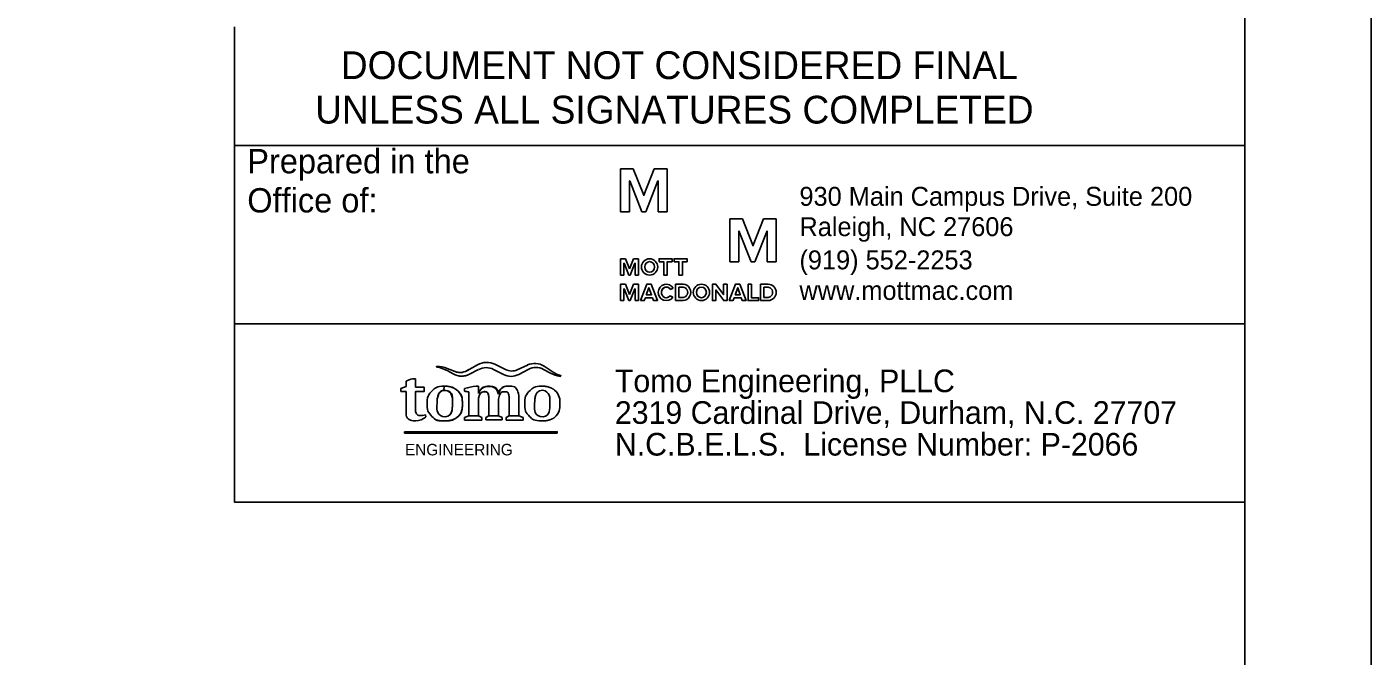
# Model space of a CAD drawing. Extents: x 2467493 to 2469404, y 649492 to 650592.
# Drawn here: x 2468926.4 to 2469192.5, y 650305.4 to 650429.9 of the extents above; entities that cross this region are included whole.
import ezdxf

# ---------------------------------------------------------------- set-up
doc = ezdxf.new("R2010")
doc.units = 0
for name, color, linetype in [('Old_Level_18', 7, 'Continuous'), ('Old_Level_2', 7, 'Continuous'), ('Old_Level_3', 7, 'Continuous'), ('Old_Level_42', 7, 'Continuous'), ('Old_Level_62', 7, 'Continuous'), ('Old_Level_63', 7, 'Continuous'), ('Sheet Sticker Exception Certification CELL', 7, 'Continuous')]:
    doc.layers.add(name, color=color, linetype=linetype)

msp = doc.modelspace()

# ---------------------------------------------------------------- linework, layer by layer
at = {"layer": 'Old_Level_18'}
msp.add_lwpolyline([(2469167.55, 650567.49), (2467667.55, 650567.49), (2467667.55, 649517.49), (2469167.55, 649517.49)], close=True, dxfattribs=at)
at = {"layer": 'Old_Level_2'}
for p, q in [((2469046.48, 650401.84), (2469043.96, 650401.84)), ((2469043.96, 650401.84), (2469043.96, 650393.34)), ((2469048.53, 650396.59), (2469046.48, 650401.84)), ((2469050.64, 650401.84), (2469048.58, 650396.59)), ((2469053.16, 650401.84), (2469050.64, 650401.84)), ((2469053.16, 650393.34), (2469053.16, 650401.84)), ((2469045.75, 650393.34), (2469045.75, 650399.45)), ((2469045.75, 650399.45), (2469045.78, 650399.45)), ((2469045.78, 650399.45), (2469048.17, 650393.34)), ((2469048.95, 650393.34), (2469051.34, 650399.48)), ((2469051.34, 650399.48), (2469051.37, 650399.48)), ((2469051.37, 650399.48), (2469051.37, 650393.34)), ((2469048.53, 650396.51), (2469048.53, 650396.59)), ((2469048.58, 650396.51), (2469048.53, 650396.51)), ((2469048.58, 650396.59), (2469048.58, 650396.51)), ((2469043.96, 650393.34), (2469045.75, 650393.34)), ((2469048.17, 650393.34), (2469048.95, 650393.34)), ((2469051.37, 650393.34), (2469053.16, 650393.34)), ((2469068.09, 650391.94), (2469065.57, 650391.94)), ((2469065.57, 650391.94), (2469065.57, 650383.44)), ((2469070.15, 650386.69), (2469068.09, 650391.94)), ((2469072.25, 650391.94), (2469070.2, 650386.69)), ((2469074.77, 650391.94), (2469072.25, 650391.94)), ((2469074.77, 650383.44), (2469074.77, 650391.94)), ((2469067.37, 650383.44), (2469067.37, 650389.55)), ((2469067.37, 650389.55), (2469067.39, 650389.55)), ((2469067.39, 650389.55), (2469069.78, 650383.44)), ((2469070.56, 650383.44), (2469072.95, 650389.57)), ((2469072.95, 650389.57), (2469072.98, 650389.57)), ((2469072.98, 650389.57), (2469072.98, 650383.44)), ((2469070.15, 650386.61), (2469070.15, 650386.69)), ((2469070.2, 650386.61), (2469070.15, 650386.61)), ((2469070.2, 650386.69), (2469070.2, 650386.61)), ((2469044.92, 650384.04), (2469043.96, 650384.04)), ((2469043.96, 650384.04), (2469043.96, 650380.79)), ((2469045.72, 650382.01), (2469044.92, 650384.04)), ((2469046.53, 650384.04), (2469045.72, 650382.01)), ((2469047.49, 650384.04), (2469046.53, 650384.04)), ((2469047.49, 650380.79), (2469047.49, 650384.04)), ((2469047.49, 650380.79), (2469047.49, 650384.04)), ((2469065.57, 650383.44), (2469067.37, 650383.44)), ((2469069.78, 650383.44), (2469070.56, 650383.44)), ((2469072.98, 650383.44), (2469074.77, 650383.44)), ((2469043.96, 650380.79), (2469044.63, 650380.79)), ((2469044.63, 650380.79), (2469044.63, 650383.13)), ((2469044.63, 650383.13), (2469044.66, 650383.13)), ((2469044.63, 650383.13), (2469044.66, 650383.13)), ((2469044.66, 650383.13), (2469045.57, 650380.79)), ((2469045.57, 650380.79), (2469045.88, 650380.79)), ((2469045.88, 650380.79), (2469046.79, 650383.13)), ((2469046.79, 650383.13), (2469046.82, 650383.13)), ((2469046.79, 650383.13), (2469046.82, 650383.13)), ((2469046.79, 650383.13), (2469046.82, 650383.13)), ((2469046.82, 650383.13), (2469046.82, 650380.79)), ((2469046.82, 650380.79), (2469047.49, 650380.79)), ((2469044.92, 650378.99), (2469043.96, 650378.99)), ((2469043.96, 650378.99), (2469043.96, 650375.74)), ((2469044.63, 650375.74), (2469044.63, 650378.08)), ((2469044.63, 650378.08), (2469044.66, 650378.08)), ((2469044.66, 650378.08), (2469045.57, 650375.74)), ((2469045.72, 650376.96), (2469044.92, 650378.99)), ((2469046.53, 650378.99), (2469045.72, 650376.96)), ((2469045.88, 650375.74), (2469046.79, 650378.08)), ((2469047.49, 650378.99), (2469046.53, 650378.99)), ((2469046.79, 650378.08), (2469046.82, 650378.08)), ((2469046.82, 650378.08), (2469046.82, 650375.74)), ((2469047.49, 650375.74), (2469047.49, 650378.99)), ((2469053.83, 650377.93), (2469054.4, 650378.2)), ((2469053.83, 650377.93), (2469054.4, 650378.2)), ((2469056.33, 650378.99), (2469054.85, 650378.99)), ((2469054.85, 650378.99), (2469054.85, 650377.31)), ((2469055.52, 650376.37), (2469055.52, 650378.39)), ((2469055.52, 650378.39), (2469056.33, 650378.39)), ((2469071.67, 650378.99), (2469071.67, 650378.99)), ((2469073.15, 650378.99), (2469071.67, 650378.99)), ((2469071.67, 650378.99), (2469071.67, 650377.31)), ((2469072.34, 650376.37), (2469072.34, 650378.39)), ((2469072.34, 650378.39), (2469073.15, 650378.39)), ((2469073.15, 650378.37), (2469073.15, 650378.37)), ((2469043.96, 650375.74), (2469044.63, 650375.74)), ((2469045.57, 650375.74), (2469045.88, 650375.74)), ((2469046.82, 650375.74), (2469047.49, 650375.74)), ((2469054.32, 650376.41), (2469053.76, 650376.69)), ((2469054.32, 650376.41), (2469053.76, 650376.69)), ((2469054.85, 650377.31), (2469054.85, 650375.74)), ((2469054.85, 650375.74), (2469056.33, 650375.74)), ((2469056.33, 650376.37), (2469055.52, 650376.37)), ((2469071.67, 650377.31), (2469071.67, 650375.74)), ((2469071.67, 650375.74), (2469073.15, 650375.74)), ((2469073.15, 650376.37), (2469072.34, 650376.37))]:
    msp.add_line(p, q, dxfattribs=at)
for points in [[(2469051.57, 650383.44), (2469052.51, 650383.44), (2469052.51, 650380.79), (2469053.21, 650380.79), (2469053.21, 650383.44), (2469054.15, 650383.44), (2469054.15, 650384.04), (2469051.57, 650384.04), (2469051.57, 650383.44)], [(2469054.56, 650383.44), (2469055.5, 650383.44), (2469055.5, 650380.79), (2469056.2, 650380.79), (2469056.2, 650383.44), (2469057.14, 650383.44), (2469057.14, 650384.04), (2469054.56, 650384.04), (2469054.56, 650383.44)], [(2469047.88, 650375.74), (2469048.66, 650375.74), (2469048.87, 650376.29), (2469050.27, 650376.29), (2469050.48, 650375.74), (2469051.24, 650375.74), (2469049.99, 650378.99), (2469049.13, 650378.99), (2469047.88, 650375.74)], [(2469049.05, 650376.89), (2469049.57, 650378.29), (2469050.09, 650376.89), (2469049.05, 650376.89)], [(2469062.8, 650377.85), (2469062.83, 650377.85), (2469064.39, 650375.74), (2469065.04, 650375.74), (2469065.04, 650378.99), (2469064.36, 650378.99), (2469064.36, 650376.94), (2469062.83, 650378.99), (2469062.15, 650378.99), (2469062.15, 650375.74), (2469062.8, 650375.74), (2469062.8, 650377.85)], [(2469065.45, 650375.74), (2469066.23, 650375.74), (2469066.44, 650376.29), (2469067.85, 650376.29), (2469068.05, 650375.74), (2469068.81, 650375.74), (2469067.56, 650378.99), (2469066.7, 650378.99), (2469065.45, 650375.74)], [(2469066.62, 650376.89), (2469067.14, 650378.29), (2469067.66, 650376.89), (2469066.62, 650376.89)], [(2469071.28, 650375.74), (2469071.28, 650376.32), (2469069.87, 650376.32), (2469069.87, 650378.99), (2469069.2, 650378.99), (2469069.2, 650375.74), (2469071.28, 650375.74)], [(2469071.28, 650375.74), (2469071.28, 650376.32), (2469069.87, 650376.32), (2469069.87, 650378.99), (2469069.2, 650378.99), (2469069.2, 650375.74), (2469071.28, 650375.75), (2469071.28, 650376.32)]]:
    msp.add_lwpolyline(points, dxfattribs=at)
msp.add_arc((2469073.15, 650377.37), 1.62, 270, 90, dxfattribs=at)
for centre, major_axis, ratio in [((2469049.7, 650382.41), (0, 1.62), 0.993118), ((2469049.7, 650382.41), (0, 1.06), 0.916103), ((2469059.97, 650377.37), (0, 1.62), 0.993118), ((2469059.97, 650377.37), (0, 1.06), 0.916103)]:
    msp.add_ellipse(centre, major_axis=major_axis, ratio=ratio, dxfattribs=at)
for centre, major_axis, ratio, start_param, end_param in [((2469053.01, 650377.37), (0, 1.62), 0.993118, 5.246647, 10.366427), ((2469053.01, 650377.37), (0, 1.62), 0.993118, 5.246647, 10.366427), ((2469053.01, 650377.37), (0, 1.06), 0.916103, 5.276876, 9.424778), ((2469053.01, 650377.37), (0, 1.06), 0.916103, 5.276876, 10.296021), ((2469056.33, 650377.37), (0, -1.62), 0.930276, 0, 3.141593), ((2469056.33, 650377.38), (0, -1.01), 0.900832, 0, 3.141593), ((2469073.15, 650377.38), (0, -1.01), 0.900832, 0, 3.141593), ((2469053.01, 650377.37), (0, 1.06), 0.916103, 3.141593, 4.012835)]:
    msp.add_ellipse(centre, major_axis=major_axis, ratio=ratio, start_param=start_param, end_param=end_param, dxfattribs=at)
at = {"layer": 'Old_Level_3'}
for p, q in [((2469009.61, 650361.9), (2469010.81, 650361.22)), ((2469009.61, 650361.9), (2469010.81, 650361.22)), ((2469009.64, 650362.33), (2469011.2, 650361.7)), ((2469011.2, 650361.7), (2469009.64, 650362.33)), ((2469013.54, 650361.86), (2469015.64, 650363.05)), ((2469015.64, 650363.05), (2469013.54, 650361.86)), ((2469014.06, 650361.18), (2469015.86, 650362.11)), ((2469014.06, 650361.18), (2469015.86, 650362.11)), ((2469018.8, 650362.12), (2469020.76, 650361.11)), ((2469018.8, 650362.12), (2469020.76, 650361.11)), ((2469019.09, 650363.14), (2469021.2, 650362.09)), ((2469021.2, 650362.09), (2469019.09, 650363.14)), ((2469025.54, 650362.99), (2469023.51, 650362.05)), ((2469025.54, 650362.99), (2469023.51, 650362.05)), ((2469025.68, 650362.13), (2469023.79, 650361.13)), ((2469023.79, 650361.13), (2469025.68, 650362.13)), ((2469030.08, 650361.4), (2469028.72, 650362.12)), ((2469028.72, 650362.12), (2469030.08, 650361.4)), ((2469028.81, 650362.75), (2469030.6, 650361.57)), ((2469030.6, 650361.57), (2469028.81, 650362.75)), ((2469001.49, 650359.81), (2469001.49, 650358.77)), ((2469001.49, 650359.81), (2469001.49, 650358.77)), ((2469002.74, 650360.26), (2469003.38, 650360.26)), ((2469003.38, 650360.26), (2469002.74, 650360.26)), ((2469003.38, 650360.26), (2469003.38, 650358.63)), ((2469003.38, 650358.63), (2469003.38, 650360.26)), ((2469000.44, 650358.31), (2469001.49, 650358.77)), ((2469001.49, 650358.77), (2469000.44, 650358.31)), ((2469000.44, 650357.76), (2469000.44, 650358.31)), ((2469000.44, 650358.31), (2469000.44, 650357.76)), ((2469001.48, 650357.76), (2469000.44, 650357.76)), ((2469000.44, 650357.76), (2469001.48, 650357.76)), ((2469001.48, 650353.35), (2469001.48, 650357.76)), ((2469001.48, 650357.76), (2469001.48, 650353.35)), ((2469003.38, 650358.63), (2469005.08, 650358.63)), ((2469005.08, 650358.63), (2469003.38, 650358.63)), ((2469009.06, 650358.82), (2469008.97, 650357.97)), ((2469009.06, 650358.82), (2469009.06, 650358.82)), ((2469013.08, 650358.32), (2469013.08, 650357.79)), ((2469013.08, 650358.32), (2469013.08, 650357.79)), ((2469015.37, 650358.78), (2469015.81, 650358.78)), ((2469015.81, 650358.78), (2469015.37, 650358.78)), ((2469015.81, 650358.78), (2469015.81, 650357.32)), ((2469015.81, 650357.32), (2469015.81, 650358.78)), ((2469002.9, 650351.95), (2469003.43, 650351.96)), ((2469002.9, 650351.95), (2469003.43, 650351.96)), ((2469005.32, 650353.14), (2469005.4, 650352.7)), ((2469005.4, 650352.7), (2469005.32, 650353.14)), ((2469013.08, 650352.6), (2469013.91, 650352.93)), ((2469013.91, 650352.93), (2469013.08, 650352.6)), ((2469013.08, 650352.09), (2469013.08, 650352.6)), ((2469013.08, 650352.6), (2469013.08, 650352.6)), ((2469013.08, 650352.6), (2469013.08, 650352.09)), ((2469013.08, 650352.09), (2469016.47, 650352.09)), ((2469013.08, 650352.09), (2469016.47, 650352.09)), ((2469015.82, 650352.93), (2469013.91, 650352.93)), ((2469016.47, 650352.6), (2469015.82, 650352.93)), ((2469016.47, 650352.6), (2469015.82, 650352.93)), ((2469016.47, 650352.09), (2469016.47, 650352.6)), ((2469016.47, 650352.6), (2469016.47, 650352.6)), ((2469016.47, 650352.09), (2469016.47, 650352.6)), ((2469017.12, 650352.62), (2469017.12, 650352.62)), ((2469017.25, 650352.62), (2469017.9, 650352.94)), ((2469017.9, 650352.94), (2469017.25, 650352.62)), ((2469017.25, 650352.11), (2469017.25, 650352.62)), ((2469017.25, 650352.62), (2469017.25, 650352.11)), ((2469017.25, 650352.11), (2469020.51, 650352.11)), ((2469017.25, 650352.11), (2469020.51, 650352.11)), ((2469019.82, 650352.94), (2469017.9, 650352.94)), ((2469020.51, 650352.62), (2469019.82, 650352.94)), ((2469020.51, 650352.62), (2469019.82, 650352.94)), ((2469020.51, 650352.11), (2469020.51, 650352.62)), ((2469020.51, 650352.62), (2469020.51, 650352.62)), ((2469020.51, 650352.11), (2469020.51, 650352.62)), ((2469021.09, 650352.6), (2469021.09, 650352.6)), ((2469021.3, 650352.6), (2469021.92, 650352.92)), ((2469021.92, 650352.92), (2469021.3, 650352.6)), ((2469021.3, 650352.09), (2469021.3, 650352.6)), ((2469021.3, 650352.6), (2469021.3, 650352.09)), ((2469021.3, 650352.09), (2469024.69, 650352.09)), ((2469021.3, 650352.09), (2469024.69, 650352.09)), ((2469023.83, 650352.92), (2469021.92, 650352.92)), ((2469024.69, 650352.6), (2469023.83, 650352.92)), ((2469024.69, 650352.6), (2469023.83, 650352.92)), ((2469024.48, 650352.6), (2469024.48, 650352.6)), ((2469024.69, 650352.09), (2469024.69, 650352.6)), ((2469024.69, 650352.09), (2469024.69, 650352.6)), ((2469031.41, 650349.8), (2469001.21, 650349.79)), ((2469031.41, 650349.8), (2469001.21, 650349.79)), ((2469001.21, 650349.79), (2469001.21, 650349.5)), ((2469001.21, 650349.79), (2469001.21, 650349.5)), ((2469001.21, 650349.5), (2469031.41, 650349.5)), ((2469001.21, 650349.5), (2469031.41, 650349.5)), ((2469031.41, 650349.5), (2469031.41, 650349.8)), ((2469031.41, 650349.5), (2469031.41, 650349.8)), ((2469031.41, 650349.5), (2469031.41, 650349.5))]:
    msp.add_line(p, q, dxfattribs=at)
for points in [[(2469167.55, 650335.84), (2468967.5, 650335.84), (2468967.5, 650371.14)], [(2469005.08, 650358.63), (2469005.08, 650357.76), (2469003.37, 650357.76), (2469003.37, 650353.95)], [(2469003.37, 650353.95), (2469003.37, 650357.76), (2469005.08, 650357.76), (2469005.08, 650358.63)], [(2469015.82, 650356.41), (2469015.82, 650352.93), (2469013.91, 650352.93), (2469013.91, 650357.66)], [(2469013.91, 650357.66), (2469013.91, 650352.93), (2469015.82, 650352.93), (2469015.82, 650356.41)], [(2469019.82, 650356.22), (2469019.82, 650352.94), (2469017.9, 650352.94), (2469017.9, 650355.93)], [(2469017.9, 650355.93), (2469017.9, 650352.94), (2469019.82, 650352.94), (2469019.82, 650356.22)], [(2469023.83, 650356.23), (2469023.83, 650352.92), (2469021.92, 650352.92), (2469021.92, 650355.89)], [(2469021.92, 650355.89), (2469021.92, 650352.92), (2469023.83, 650352.92), (2469023.83, 650356.23)]]:
    msp.add_lwpolyline(points, dxfattribs=at)
for centre, radius, start, end in [((2469007.59, 650362.65), 0.0758, 89.4701, 262.0204), ((2469007.59, 650362.65), 0.0758, 89.4701, 262.0204), ((2469006.78, 650356.84), 5.79, 60.7255, 82.0204), ((2469006.78, 650356.84), 5.79, 60.7255, 82.0204), ((2469007.54, 650357.09), 5.64, 68.211, 89.4701), ((2469007.54, 650357.09), 5.64, 68.211, 89.4701), ((2469012.2, 650364.22), 2.71, 248.211, 308.9356), ((2469017.45, 650359.86), 3.66, 63.4105, 119.5442), ((2469017.45, 650359.86), 3.66, 63.4105, 119.5442), ((2469017.34, 650359.28), 3.19, 62.7919, 117.5568), ((2469017.34, 650359.28), 3.19, 62.7919, 117.5568), ((2469022.39, 650364.47), 2.67, 243.4105, 294.8953), ((2469022.39, 650364.47), 2.67, 243.4105, 294.8953), ((2469026.96, 650359.94), 3.37, 56.5776, 114.8953), ((2469026.96, 650359.94), 3.37, 56.5776, 114.8953), ((2469027.2, 650359.26), 3.24, 61.9151, 117.8233), ((2469027.2, 650359.26), 3.24, 61.9151, 117.8233), ((2469004.14, 650354.41), 6.01, 103.443, 116.1707), ((2469004.14, 650354.41), 6.01, 103.443, 116.1707), ((2469012.48, 650364.2), 3.41, 240.7255, 299.8298), ((2469012.48, 650364.2), 3.41, 240.7255, 297.5568), ((2469012.2, 650364.22), 2.71, 248.211, 299.5442), ((2469022.26, 650364.02), 3.27, 242.7919, 297.8233), ((2469022.26, 650364.02), 3.27, 242.7919, 297.8233), ((2469033.02, 650366.9), 6.24, 241.9151, 260.5433), ((2469033.02, 650366.9), 6.24, 241.9151, 260.5433), ((2469033.05, 650365.29), 4.46, 236.5776, 256.8197), ((2469033.05, 650365.29), 4.46, 236.5776, 256.8197), ((2469032.01, 650360.85), 0.105, 260.5433, 76.8197), ((2469032.01, 650360.85), 0.105, 260.5433, 76.8197), ((2469015.74, 650351.06), 7.73, 92.7753, 110.1143), ((2469015.74, 650351.06), 7.73, 92.7753, 110.1143), ((2469019.52, 650395.88), 38.63, 260.395, 261.6509), ((2469019.52, 650395.88), 38.63, 260.395, 261.6509), ((2469004.47, 650353.95), 1.1, 180, 216.038), ((2469004.47, 650353.95), 1.1, 180, 214.5443), ((2469002.88, 650353.35), 1.4, 180, 270.9178), ((2469002.88, 650353.35), 1.4, 180, 270.9178), ((2469003.38, 650355.1), 3.14, 270.9178, 309.9754), ((2469003.38, 650355.1), 3.14, 270.9178, 309.9754), ((2469004.21, 650353.77), 0.784, 214.2431, 269.2019), ((2469004.21, 650353.77), 0.784, 214.2431, 269.2019), ((2469004.25, 650356.7), 3.71, 269.2019, 286.6975), ((2469004.25, 650356.7), 3.71, 269.2019, 286.6975)]:
    msp.add_arc(centre, radius, start, end, dxfattribs=at)
for points, degree in [([(2469009.06, 650358.82), (2469007.61, 650358.82), (2469006.64, 650357.87), (2469005.67, 650356.92), (2469005.67, 650355.34), (2469005.67, 650353.79), (2469006.62, 650352.82), (2469007.57, 650351.85), (2469009.06, 650351.95)], 3), ([(2469009.06, 650358.82), (2469010.46, 650358.82), (2469011.58, 650358.04), (2469012.65, 650357.01), (2469012.64, 650355.33), (2469012.62, 650353.46), (2469011.57, 650352.6), (2469010.43, 650351.85), (2469009.06, 650351.95), (2469007.57, 650351.85), (2469006.62, 650352.82), (2469005.67, 650353.79), (2469005.67, 650355.34), (2469005.67, 650356.92), (2469006.64, 650357.87), (2469007.61, 650358.82), (2469009.06, 650358.82)], 3), ([(2469009.32, 650352.72), (2469007.49, 650352.87), (2469007.64, 650355.36), (2469007.64, 650356.35), (2469007.85, 650356.96), (2469008.18, 650357.92), (2469009.19, 650358)], 3), ([(2469009.32, 650352.72), (2469010.69, 650352.99), (2469010.62, 650355.4), (2469010.74, 650357.72), (2469009.19, 650358), (2469008.18, 650357.92), (2469007.85, 650356.96), (2469007.64, 650356.35), (2469007.64, 650355.36), (2469007.49, 650352.87), (2469009.32, 650352.72)], 3), ([(2469011.58, 650358.04), (2469010.46, 650358.82), (2469009.06, 650358.82)], 2), ([(2469009.19, 650358), (2469010.74, 650357.72), (2469010.62, 650355.4), (2469010.69, 650352.99), (2469009.32, 650352.72)], 3), ([(2469011.57, 650352.6), (2469012.62, 650353.46), (2469012.64, 650355.33), (2469012.65, 650357.01), (2469011.58, 650358.04)], 3), ([(2469015.81, 650357.32), (2469016.36, 650358.74), (2469017.91, 650358.8), (2469019.44, 650358.69), (2469019.72, 650357.25), (2469020.35, 650358.79), (2469021.89, 650358.81), (2469023.07, 650358.77), (2469023.52, 650357.96), (2469023.84, 650357.31), (2469023.83, 650356.23)], 3), ([(2469017.91, 650358.8), (2469016.36, 650358.74), (2469015.81, 650357.32)], 2), ([(2469017.9, 650355.93), (2469017.92, 650356.75), (2469017.76, 650357.12), (2469017.68, 650357.72), (2469016.98, 650357.73), (2469016.03, 650357.59), (2469015.82, 650356.41)], 3), ([(2469015.82, 650356.41), (2469016.03, 650357.59), (2469016.98, 650357.73)], 2), ([(2469016.98, 650357.73), (2469017.68, 650357.72), (2469017.76, 650357.12)], 2), ([(2469017.76, 650357.12), (2469017.92, 650356.75), (2469017.9, 650355.93)], 2), ([(2469019.72, 650357.25), (2469019.44, 650358.69), (2469017.91, 650358.8)], 2), ([(2469023.83, 650356.23), (2469023.84, 650357.31), (2469023.52, 650357.96), (2469023.07, 650358.77), (2469021.89, 650358.81), (2469020.35, 650358.79), (2469019.72, 650357.25)], 3), ([(2469021.92, 650355.89), (2469021.92, 650356.54), (2469021.85, 650356.85), (2469021.71, 650357.72), (2469020.99, 650357.72), (2469019.92, 650357.63), (2469019.82, 650356.22)], 3), ([(2469019.82, 650356.22), (2469019.92, 650357.63), (2469020.99, 650357.72), (2469021.71, 650357.72), (2469021.85, 650356.85), (2469021.92, 650356.54), (2469021.92, 650355.89)], 3), ([(2469028.37, 650358.82), (2469026.92, 650358.82), (2469025.96, 650357.87), (2469024.99, 650356.92), (2469024.99, 650355.34), (2469024.99, 650353.79), (2469025.94, 650352.82), (2469026.88, 650351.85), (2469028.37, 650351.95)], 3), ([(2469028.64, 650352.72), (2469026.8, 650352.87), (2469026.96, 650355.36), (2469026.96, 650356.35), (2469027.16, 650356.96), (2469027.49, 650357.92), (2469028.5, 650358)], 3), ([(2469030.89, 650358.04), (2469029.78, 650358.82), (2469028.37, 650358.82)], 2), ([(2469028.5, 650358), (2469030.05, 650357.72), (2469029.93, 650355.4), (2469030, 650352.99), (2469028.64, 650352.72)], 3), ([(2469030.89, 650352.6), (2469031.93, 650353.46), (2469031.96, 650355.33), (2469031.96, 650357.01), (2469030.89, 650358.04)], 3), ([(2469009.06, 650351.95), (2469010.43, 650351.85), (2469011.57, 650352.6)], 2), ([(2469028.37, 650351.95), (2469029.75, 650351.85), (2469030.89, 650352.6)], 2)]:
    msp.add_open_spline(points, degree=degree, dxfattribs=at)
at = {"layer": 'Old_Level_42'}
msp.add_lwpolyline([(2469167.55, 650371.14), (2468967.5, 650371.14), (2468967.5, 650406.44)], dxfattribs=at)
msp.add_lwpolyline([(2469167.55, 650371.14), (2468967.5, 650371.14), (2468967.5, 650406.44)], dxfattribs=at)
at = {"layer": 'Old_Level_62'}
msp.add_lwpolyline([(2467517.55, 649517.49), (2469167.55, 649517.49), (2469167.55, 650567.49), (2467517.55, 650567.49)], close=True, dxfattribs=at)
at = {"layer": 'Old_Level_63'}
msp.add_lwpolyline([(2467492.55, 649492.49), (2469192.55, 649492.49), (2469192.55, 650592.49), (2467492.55, 650592.49)], close=True, dxfattribs=at)
at = {"layer": 'Sheet Sticker Exception Certification CELL'}
for p, q in [((2468967.5, 650406.44), (2468967.5, 650429.94)), ((2469167.54, 650429.93), (2469167.54, 650406.43)), ((2469167.54, 650406.44), (2468967.5, 650406.44))]:
    msp.add_line(p, q, dxfattribs=at)

# ---------------------------------------------------------------- texts
at = {"layer": 'Old_Level_2'}
for s, height, p in [('Prepared in the ', 4.8186, (2468970.05, 650400.94)), ('Office of:', 4.819, (2468970.05, 650393.19))]:
    msp.add_text(s, height=height, dxfattribs=at).set_placement(p)
for s, p in [('930 Main Campus Drive, Suite 200', (2469079.37, 650394.51)), ('Raleigh, NC 27606', (2469079.37, 650388.51)), ('(919) 552-2253', (2469079.37, 650381.93)), ('www.mottmac.com', (2469079.37, 650375.88))]:
    msp.add_text(s, height=3.75, rotation=360, dxfattribs=at).set_placement(p)
at = {"layer": 'Old_Level_3'}
for s, height, rotation, p in [('Tomo Engineering, PLLC', 4.483, 0.0019, (2469042.83, 650357.61)), ('2319 Cardinal Drive, Durham, N.C. 27707', 4.483, 0.0004, (2469042.83, 650351.34)), ('N.C.B.E.L.S.  License Number: P-2066', 4.483, 0.0004, (2469042.83, 650345.06)), ('ENGINEERING', 2.2803, 0.0004, (2469001.26, 650345.1))]:
    msp.add_text(s, height=height, rotation=rotation, dxfattribs=at).set_placement(p)
at = {"layer": 'Sheet Sticker Exception Certification CELL'}
for s, p in [('DOCUMENT NOT CONSIDERED FINAL', (2468988.57, 650419.6)), ('UNLESS ALL SIGNATURES COMPLETED', (2468983.5, 650410.8))]:
    msp.add_text(s, height=5.5, dxfattribs=at).set_placement(p)

doc.saveas('drawing.dxf')
